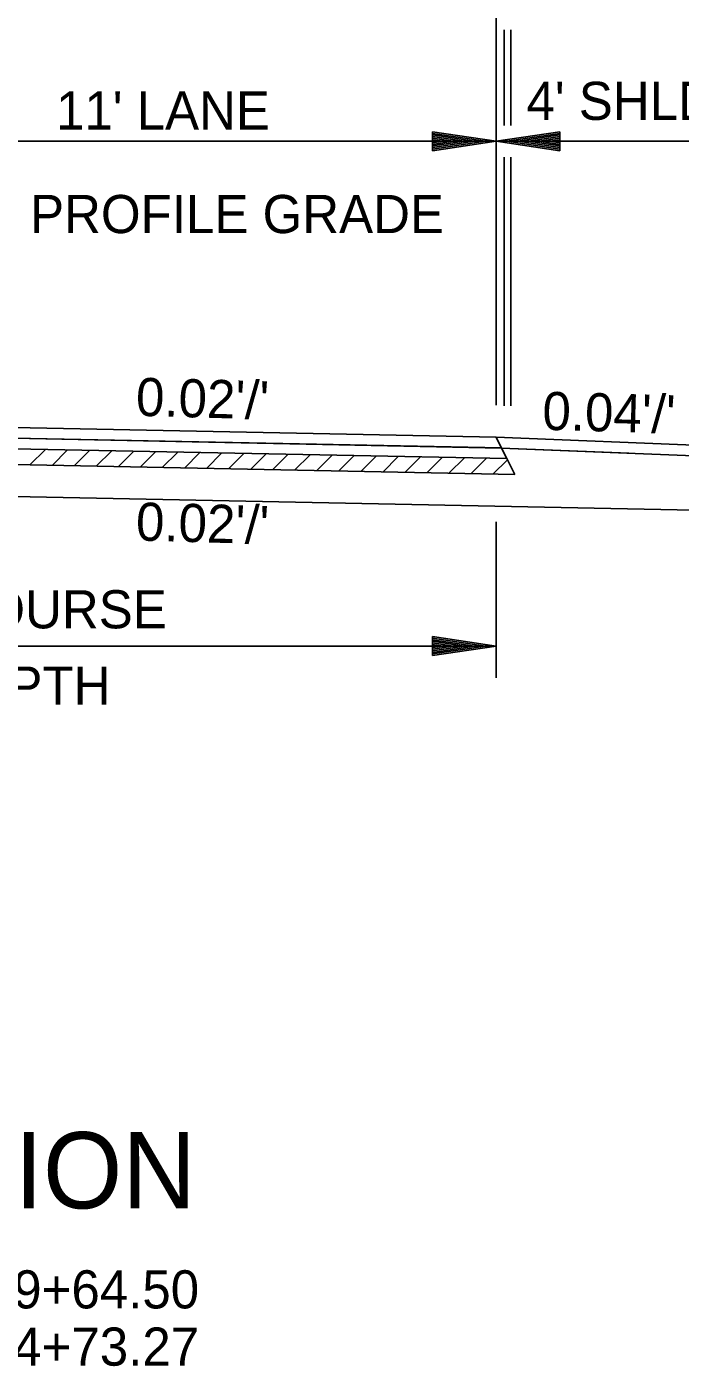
# Model space of a CAD drawing. Extents: x -900 to 15312, y 1857 to 2945.
# Drawn here: x 4100.3 to 4203.1, y 2313.4 to 2524 of the extents above; entities that cross this region are included whole.
import ezdxf

# ---------------------------------------------------------------- set-up
doc = ezdxf.new("R2010")
doc.units = 0
doc.layers.add('R_Annotation', color=7, linetype='Continuous')
doc.layers.add('R_Dimension', color=7, linetype='Continuous')

msp = doc.modelspace()

# ---------------------------------------------------------------- linework, layer by layer
at = {"layer": 'R_Annotation'}
for p, q in [((4174.16, 2459.49), (4064.16, 2461.69)), ((4175.01, 2457.81), (4064.16, 2460.02)), ((4175.85, 2456.12), (4064.16, 2458.36)), ((4174.16, 2459.49), (4177.11, 2453.6)), ((4214.16, 2457.89), (4174.16, 2459.49)), ((4177.11, 2453.6), (4064.16, 2455.86)), ((4195.01, 2456.99), (4175.01, 2457.79)), ((4282.59, 2446.49), (4064.16, 2450.86))]:
    msp.add_line(p, q, dxfattribs=at)
at = {"layer": 'R_Dimension'}
for p, q in [((4174.16, 2506.02), (4174.16, 2531.02)), ((4175.43, 2508.52), (4175.43, 2523.52)), ((4176.48, 2508.52), (4176.48, 2523.52)), ((4164.16, 2507.52), (4174.16, 2506.02)), ((4164.16, 2507.52), (4164.16, 2504.52)), ((4164.16, 2507.27), (4172.49, 2506.02)), ((4164.16, 2507.02), (4170.77, 2506.02)), ((4164.16, 2506.77), (4169.11, 2506.02)), ((4164.16, 2506.51), (4167.41, 2506.02)), ((4184.16, 2507.52), (4174.16, 2506.02)), ((4184.16, 2507.27), (4175.83, 2506.02)), ((4184.16, 2507.02), (4177.55, 2506.02)), ((4184.16, 2506.77), (4179.22, 2506.02)), ((4184.16, 2506.51), (4180.91, 2506.02)), ((4184.16, 2504.52), (4184.16, 2507.52)), ((4282.59, 2506.02), (3845.74, 2506.02)), ((4164.16, 2506.26), (4165.74, 2506.02)), ((4164.16, 2504.52), (4174.16, 2506.02)), ((4164.16, 2505.53), (4167.41, 2506.02)), ((4164.16, 2505.03), (4170.77, 2506.02)), ((4164.16, 2504.77), (4172.49, 2506.02)), ((4164.16, 2505.28), (4169.11, 2506.02)), ((4164.16, 2505.79), (4165.74, 2506.02)), ((4174.16, 2464.5), (4174.16, 2506.02)), ((4184.16, 2504.52), (4174.16, 2506.02)), ((4184.16, 2504.77), (4175.83, 2506.02)), ((4184.16, 2505.03), (4177.55, 2506.02)), ((4184.16, 2505.28), (4179.22, 2506.02)), ((4184.16, 2505.54), (4180.91, 2506.02)), ((4184.16, 2506.26), (4182.58, 2506.02)), ((4184.16, 2505.79), (4182.58, 2506.02)), ((4175.43, 2464.44), (4175.43, 2503.52)), ((4176.48, 2464.44), (4176.48, 2503.52)), ((4174.16, 2459.49), (4064.16, 2461.69)), ((4064.16, 2460.02), (4175.01, 2457.79)), ((4175.01, 2457.79), (4064.16, 2460.02)), ((4064.16, 2458.36), (4175.85, 2456.12)), ((4175.01, 2457.79), (4174.16, 2459.49)), ((4174.16, 2459.49), (4175.01, 2457.79)), ((4214.16, 2457.89), (4174.16, 2459.49)), ((4100.85, 2455.12), (4103.31, 2457.57)), ((4104.32, 2455.05), (4106.77, 2457.5)), ((4107.79, 2454.98), (4110.24, 2457.44)), ((4111.25, 2454.91), (4113.7, 2457.37)), ((4114.72, 2454.85), (4117.17, 2457.3)), ((4118.18, 2454.78), (4120.64, 2457.23)), ((4121.65, 2454.71), (4124.1, 2457.16)), ((4125.12, 2454.64), (4127.57, 2457.09)), ((4128.58, 2454.57), (4131.03, 2457.02)), ((4132.05, 2454.5), (4134.5, 2456.95)), ((4135.52, 2454.43), (4137.97, 2456.88)), ((4138.98, 2454.36), (4141.43, 2456.81)), ((4142.45, 2454.29), (4144.9, 2456.74)), ((4145.91, 2454.22), (4148.37, 2456.67)), ((4149.38, 2454.15), (4151.83, 2456.6)), ((4152.85, 2454.08), (4155.3, 2456.53)), ((4156.31, 2454.01), (4158.76, 2456.47)), ((4159.78, 2453.94), (4162.23, 2456.4)), ((4163.25, 2453.87), (4165.7, 2456.33)), ((4166.71, 2453.81), (4169.16, 2456.26)), ((4170.18, 2453.74), (4172.63, 2456.19)), ((4173.64, 2453.67), (4175.93, 2455.95)), ((4175.85, 2456.12), (4175.01, 2457.79)), ((4175.01, 2457.79), (4215.01, 2456.19)), ((4174.16, 2421.65), (4174.16, 2446.16)), ((4174.16, 2426.65), (3954.16, 2426.65)), ((4164.16, 2428.15), (4174.16, 2426.65)), ((4164.16, 2428.15), (4164.16, 2425.15)), ((4164.16, 2427.9), (4172.49, 2426.65)), ((4164.16, 2427.64), (4170.77, 2426.65)), ((4164.16, 2427.39), (4169.11, 2426.65)), ((4164.16, 2427.13), (4167.41, 2426.65)), ((4164.16, 2426.88), (4165.74, 2426.65)), ((4164.16, 2425.15), (4174.16, 2426.65)), ((4164.16, 2426.16), (4167.41, 2426.65)), ((4164.16, 2425.65), (4170.77, 2426.65)), ((4164.16, 2425.4), (4172.49, 2426.65)), ((4164.16, 2425.9), (4169.11, 2426.65)), ((4164.16, 2426.41), (4165.74, 2426.65))]:
    msp.add_line(p, q, dxfattribs=at)

# ---------------------------------------------------------------- texts
at = {"layer": 'R_Annotation'}
for s, height, p in [("4' SHLD.", 6, (4178.92, 2509.38)), ("11' LANE", 6, (4104.94, 2507.86)), ('PROFILE GRADE', 6, (4100.86, 2491.58)), ('22\'-0" AGGREGATE BASE COURSE', 6, (3988.68, 2429.43)), ('(CLASS 7) - 6" COMP\'D. DEPTH', 6, (3995.44, 2417.43)), ('TANGENT SECTION', 12, (3974.51, 2338.22)), ('STA. 109+64.50', 6, (4069.23, 2322.49)), ('STA. 114+73.27', 6, (4069.23, 2313.49))]:
    msp.add_text(s, height=height, dxfattribs=at).set_placement(p)
for s, p in [("0.02'/'", (4117.45, 2462.86)), ("0.04'/'", (4181.36, 2460.66)), ("0.02'/'", (4117.45, 2443.25))]:
    msp.add_text(s, height=6, rotation=358.3978, dxfattribs=at).set_placement(p)

doc.saveas('drawing.dxf')
